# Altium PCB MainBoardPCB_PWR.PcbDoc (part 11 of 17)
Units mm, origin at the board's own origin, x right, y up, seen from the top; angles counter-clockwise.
Board outline 333.63 x 349.38 mm, 16 copper layers (L1, L2 (GND), L3 (Sign), L4 (GND), L5 (Sign), L6 (PWR/GND), L7(PWR/GND), L8 (PWR/GND), L9 (PWR/GND), L10 (PWR/GND), L11 (PWR/GND), L12 (Sign), L13 (GND), L14 (Sign), L15 (GND), L16), stack 2.503 mm thick; 2187 components, 1615 nets, 7987 pads, 1695 vias.
Unrouted connection lines stored in the file: 4757.
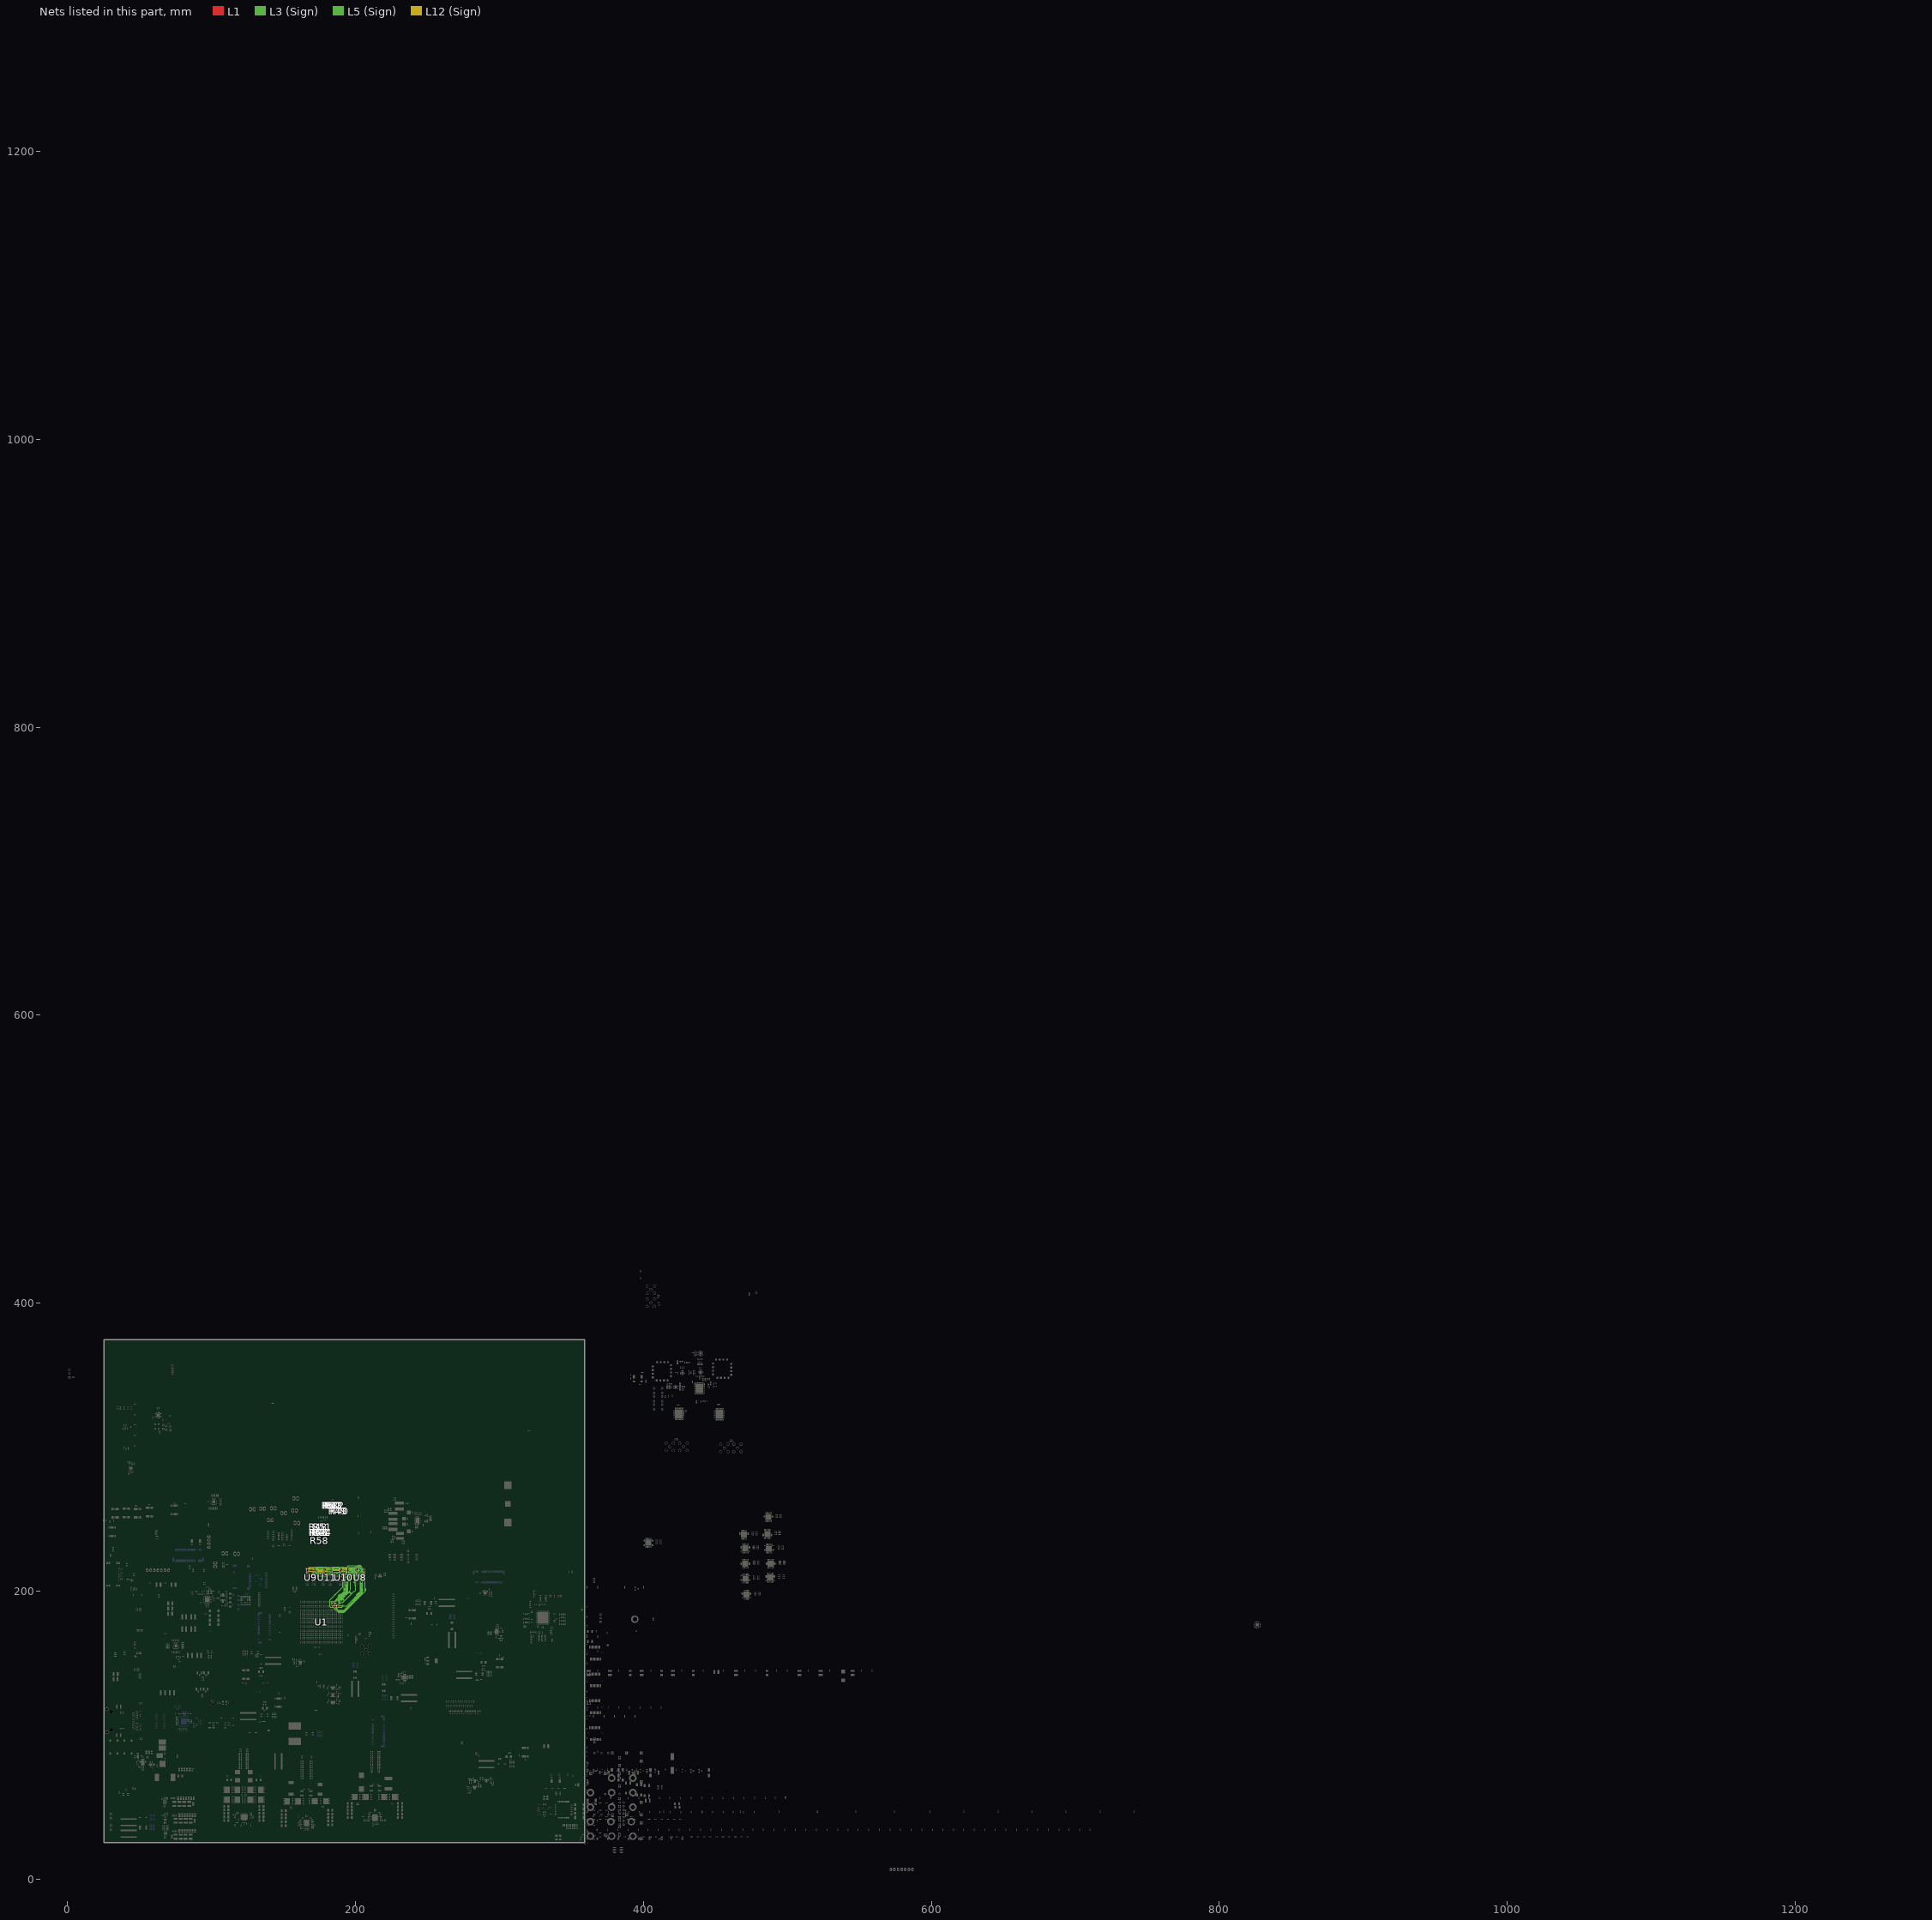
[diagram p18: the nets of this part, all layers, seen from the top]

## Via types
v1: diameter 0.5, hole 0.2, L1 to L16, 786 vias
v2: diameter 0.5/0.35/0.35/0.35/0.35/0.35/0.35/0.35/0.35/0.35/0.35/0.35/0.35/0.35/0.35/0.5 (per signal layer), hole 0.15, L1 to L16, tented both sides, 164 vias
v3: diameter 2.54, hole 1.02, L1 to L16, 152 vias
v4: diameter 0.5/0.35/0.35/0.35/0.35/0.35/0.35/0.35/0.35/0.35/0.35/0.35/0.35/0.35/0.35/0.5 (per signal layer), hole 0.2, L1 to L16, tented both sides, 100 vias
v5: diameter 0.45, hole 0.15, L1 to L16, 79 vias
v6: diameter 0.35/0/0.35 (per signal layer), hole 0.127, L1 to L3 (Sign), tented both sides, 78 vias
v7: diameter 0.45/0.45/0.45/0.45/0.45/0.45/0.45/0.45/0.45/0.45/0.45/0.45/0.45/0.45/0.45/0.45 (per signal layer), hole 0.15, L1 to L16, 65 vias
v8: diameter 0.4, hole 0.15, L1 to L16, 61 vias
v9: diameter 0.2, hole 0.1, L1 to L16, 35 vias
v10: diameter 0.5, hole 0.2, L1 to L16, tented both sides, 32 vias
v11: diameter 0.2/0/0.2 (per signal layer), hole 0.1, L1 to L3 (Sign), 28 vias
v12: diameter 0.4, hole 0.2, L1 to L16, 16 vias
v13: diameter 0.25, hole 0.2, L1 to L16, 16 vias
v14: diameter 0.3, hole 0.2, L1 to L16, 15 vias
v15: diameter 0.5/0.35/0.35/0.35/0.35/0.35/0.35/0.35/0.35/0.35/0.35/0.35/0.35/0.35/0.35/0.45 (per signal layer), hole 0.15, L1 to L16, tented both sides, 10 vias
v16: diameter 5, hole 3, L1 to L16, 9 vias
v17: diameter 0.2/0/0.2 (per signal layer), hole 0.1, L1 to L3 (Sign), tented both sides, 9 vias
v18: diameter 0.35/0/0.35 (per signal layer), hole 0.127, L1 to L3 (Sign), 7 vias
v19: diameter 0.35/0/0.35 (per signal layer), hole 0.127, L14 (Sign) to L16, tented both sides, 5 vias
v20: diameter 1.65, hole 1.65, L1 to L16, 4 vias
v21: diameter 1.15, hole 1.15, L1 to L16, 4 vias
v22: diameter 0.35, hole 0.127, L1 to L2 (GND), 2 vias
v23: diameter 0.4, hole 0.2, L1 to L16, tented both sides, 2 vias
v24: diameter 0.35, hole 0.127, L1 to L2 (GND), tented both sides, 2 vias
v25: diameter 0.508, hole 0.127, L1 to L2 (GND), 2 vias
v26: diameter 0.508, hole 0.127, L2 (GND) to L3 (Sign), 2 vias
v27: diameter 0.35, hole 0.127, L3 (Sign) to L6 (PWR/GND), tented both sides, 2 vias
v28: diameter 0.5, hole 0.2, L3 (Sign) to L6 (PWR/GND), tented both sides, 2 vias
v29: diameter 5.5, hole 3.5, L1 to L16, 1 vias
v30: diameter 0.45/0.45/0.45 (per signal layer), hole 0.15, L1 to L3 (Sign), 1 vias
v31: diameter 0.35/0.35/0.35 (per signal layer), hole 0.127, L1 to L3 (Sign), tented both sides, 1 vias
v32: diameter 0.45/0/0.45 (per signal layer), hole 0.15, L1 to L3 (Sign), tented both sides, 1 vias
v33: diameter 0.45/0/0.45 (per signal layer), hole 0.2, L14 (Sign) to L16, tented both sides, 1 vias
v34: diameter 0.35, hole 0.127, L2 (GND) to L3 (Sign), 1 vias

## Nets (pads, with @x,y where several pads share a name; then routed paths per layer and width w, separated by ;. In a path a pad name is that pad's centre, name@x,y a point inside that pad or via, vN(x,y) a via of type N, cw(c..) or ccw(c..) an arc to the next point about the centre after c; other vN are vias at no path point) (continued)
DDR4_A5: R41.1 U1.AK27 U8.P5 U9.P5 U10.P5 U11.P5 | length 97.8
  L1 w0.116: U9.P5@166.406,213.848 166.802,214.245 v2(166.805,214.245) ; U11.P5@177.866,213.848 178.263,214.245 v2(178.265,214.245) ; U10.P5@189.327,213.848 189.723,214.245 v2(189.726,214.245) ; U1.AK27@190.927,189.927 v6(191.414,190.414) ; v2(200.384,214.252) U8.P5@200.787,213.848
  L12 (Sign) w0.092: 165.877,214.648 166.281,214.245 ; v2@166.802,214.245 166.281,214.245 ; v2@178.263,214.245 173.921,214.245 ; 195.936,214.77 195.787,214.77 ; v2@200.391,214.245 199.872,214.245 199.347,214.77 199.123,214.77 198.765,214.77 cw(c198.765,214.859) 198.675,214.859 198.675,215.005 ccw(c198.586,215.005) 198.586,215.094 198.317,215.094 ccw(c198.317,215.005) 198.228,215.005 198.228,214.859 cw(c198.138,214.859) 198.138,214.77 197.869,214.77 cw(c197.869,214.859) 197.78,214.859 197.78,215.005 ccw(c197.69,215.005) 197.69,215.094 197.422,215.094 ccw(c197.422,215.005) 197.332,215.005 197.332,214.77 197.332,214.235 cw(c197.242,214.235) 197.242,214.145 196.974,214.145 cw(c196.974,214.235) 196.884,214.235 196.884,214.68 ccw(c196.795,214.68) 196.795,214.77 196.05,214.77 195.787,214.77 ; 166.281,214.245 v2(166.805,214.245) 166.995,214.435 167.219,214.435 167.372,214.588 167.83,214.588 168.709,215.468 172.697,215.468 173.921,214.245 ; 173.921,214.245 178.583,214.245 ; 173.921,214.245 v2(178.265,214.245) 178.583,214.245 ; 178.583,214.245 178.981,214.643 179.832,214.643 180.657,215.468 183.655,215.468 184.366,214.757 188.689,214.757 189.202,214.245 v2(189.726,214.245) 189.916,214.435 190.139,214.435 190.293,214.588 190.75,214.588 191.63,215.468 191.694,215.468 194.424,215.468 195.089,215.468 195.787,214.77
  L3 (Sign) w0.092: v6(191.414,190.414) 191.056,190.055 189.852,190.055 189.698,189.901 189.135,189.901 188.921,190.115 188.437,190.115 188.249,190.304 188.249,190.569 188.437,190.758 188.486,190.758 188.862,191.133 188.862,191.316 189.116,191.57 189.116,191.687 188.963,191.839 188.963,191.855 188.709,192.109 188.709,192.659 188.093,193.275 188.093,193.575 188.164,193.645 ccw(c188.093,193.715) 188.164,193.785 188.158,193.791 cw(c188.228,193.861) 188.158,193.931 188.298,194.072 cw(c188.368,194.002) 188.438,194.072 188.514,193.996 188.549,193.961 ccw(c188.619,194.031) 188.69,193.961 188.83,194.101 ccw(c188.76,194.172) 188.83,194.242 188.795,194.277 188.719,194.353 cw(c188.789,194.423) 188.719,194.493 188.86,194.633 cw(c188.93,194.563) 189,194.633 189.076,194.557 189.319,194.314 ccw(c189.389,194.385) 189.459,194.314 189.6,194.455 ccw(c189.529,194.525) 189.6,194.595 189.357,194.838 189.281,194.914 cw(c189.351,194.984) 189.281,195.054 189.421,195.195 cw(c189.491,195.125) 189.561,195.195 189.637,195.119 189.88,194.876 ccw(c189.95,194.946) 190.021,194.876 190.161,195.016 ccw(c190.091,195.086) 190.161,195.157 189.918,195.399 189.842,195.475 cw(c189.912,195.546) 189.842,195.616 189.982,195.756 cw(c190.053,195.686) 190.123,195.756 190.199,195.68 190.442,195.437 ccw(c190.512,195.507) 190.582,195.437 190.722,195.578 ccw(c190.652,195.648) 190.722,195.718 190.48,195.961 190.404,196.037 cw(c190.474,196.107) 190.403,196.177 190.544,196.318 cw(c190.614,196.247) 190.684,196.318 190.76,196.242 191.003,195.999 ccw(c191.073,196.069) 191.144,195.999 191.284,196.139 ccw(c191.214,196.209) 191.284,196.279 191.041,196.522 190.965,196.598 cw(c191.035,196.668) 190.965,196.739 191.105,196.879 cw(c191.175,196.809) 191.246,196.879 191.322,196.803 191.565,196.56 ccw(c191.635,196.63) 191.705,196.56 191.845,196.7 ccw(c191.775,196.771) 191.845,196.841 191.602,197.084 191.526,197.16 cw(c191.597,197.23) 191.526,197.3 191.667,197.44 cw(c191.737,197.37) 191.807,197.44 191.883,197.364 192.126,197.122 ccw(c192.196,197.192) 192.266,197.122 192.407,197.262 ccw(c192.337,197.332) 192.407,197.402 192.164,197.645 192.088,197.721 cw(c192.158,197.791) 192.088,197.862 192.228,198.002 cw(c192.298,197.932) 192.369,198.002 192.445,197.926 192.687,197.683 ccw(c192.758,197.753) 192.828,197.683 192.968,197.823 ccw(c192.898,197.894) 192.968,197.964 192.725,198.207 192.649,198.283 cw(c192.719,198.353) 192.649,198.423 192.79,198.563 cw(c192.86,198.493) 192.93,198.563 193.006,198.487 193.249,198.244 ccw(c193.319,198.315) 193.389,198.244 193.53,198.385 ccw(c193.459,198.455) 193.53,198.525 193.287,198.768 193.211,198.844 cw(c193.281,198.914) 193.211,198.984 193.351,199.125 cw(c193.421,199.055) 193.491,199.125 193.567,199.049 193.81,198.806 ccw(c193.881,198.876) 193.951,198.806 194.091,198.946 ccw(c194.021,199.016) 194.091,199.087 193.848,199.329 193.772,199.406 cw(c193.842,199.476) 193.772,199.546 193.913,199.686 cw(c193.983,199.616) 194.053,199.686 194.129,199.61 194.372,199.367 ccw(c194.442,199.438) 194.512,199.367 194.653,199.508 ccw(c194.582,199.578) 194.653,199.648 194.48,199.821 cw(c194.55,199.891) 194.48,199.961 194.69,200.172 194.742,200.223 194.742,206.035 195.161,206.454 195.161,206.802 195.944,207.585 195.944,210.015 200.173,214.245 200.391,214.245 v2(200.384,214.252)
DDR4_A6: R43.1 U1.AF27 U8.P2 U9.P2 U10.P2 U11.P2 | length 90.7
  L1 w0.116: U9.P2@171.206,213.848 v2(171.609,214.252) ; U11.P2@182.666,213.848 v2(183.07,214.252) ; U1.AF27@186.927,189.927 v6(187.414,189.44) ; U10.P2@194.127,213.848 v1(194.53,214.252) ; U8.P2@205.587,213.848 v2(205.991,214.252)
  L5 (Sign) w0.092: v2(171.609,214.252) 171.935,214.252 172.314,214.63 179.776,214.63 180.538,213.868 182.113,213.868 182.497,214.252 v2(183.07,214.252) 183.369,214.252 183.747,214.63 191.237,214.63 191.999,213.868 193.573,213.868 193.957,214.252 v1(194.53,214.252) 194.757,214.252 195.153,214.648 195.288,214.648 ccw(c195.288,214.738) 195.377,214.738 195.377,214.812 cw(c195.467,214.812) 195.467,214.902 195.736,214.902 cw(c195.736,214.812) 195.825,214.812 195.825,214.648 195.825,214.484 ccw(c195.915,214.484) 195.915,214.394 196.183,214.394 ccw(c196.183,214.484) 196.273,214.484 196.273,214.648 196.273,214.812 cw(c196.363,214.812) 196.363,214.902 196.631,214.902 cw(c196.631,214.812) 196.721,214.812 196.721,214.648 196.721,214.575 ccw(c196.81,214.575) 196.81,214.485 197.079,214.485 ccw(c197.079,214.575) 197.169,214.575 197.169,214.648 197.169,214.812 cw(c197.258,214.812) 197.258,214.902 197.527,214.902 cw(c197.527,214.812) 197.616,214.812 197.616,214.648 197.616,214.575 ccw(c197.706,214.575) 197.706,214.485 197.975,214.485 ccw(c197.975,214.575) 198.064,214.575 198.064,214.648 198.064,214.812 cw(c198.154,214.812) 198.154,214.902 198.422,214.902 cw(c198.422,214.812) 198.512,214.812 198.512,214.648 198.512,214.575 ccw(c198.602,214.575) 198.602,214.485 198.87,214.485 ccw(c198.87,214.575) 198.96,214.575 198.96,214.648 198.96,214.812 cw(c199.049,214.812) 199.049,214.902 199.318,214.902 cw(c199.318,214.812) 199.408,214.812 199.408,214.648 199.408,214.575 ccw(c199.497,214.575) 199.497,214.485 199.766,214.485 ccw(c199.766,214.575) 199.855,214.575 199.855,214.648 199.855,214.678 cw(c199.945,214.678) 199.945,214.767 200.214,214.767 cw(c200.214,214.678) 200.303,214.678 200.303,214.648 ccw(c200.379,214.648) 200.379,214.573 200.675,214.573 ccw(c200.675,214.648) 200.751,214.648 201.199,214.648 201.199,214.639 ccw(c201.288,214.639) 201.288,214.549 201.557,214.549 ccw(c201.557,214.639) 201.647,214.639 201.647,214.648 201.647,214.812 cw(c201.736,214.812) 201.736,214.902 202.005,214.902 cw(c202.005,214.812) 202.094,214.812 202.094,214.738 ccw(c202.184,214.738) 202.184,214.648 202.578,214.648 202.679,214.648 203.474,213.853 203.608,213.853 cw(c203.608,213.763) 203.698,213.763 ccw(c203.787,213.763) 203.787,213.674 204.056,213.674 ccw(c204.056,213.763) 204.146,213.763 204.146,213.77 cw(c204.229,213.77) 204.229,213.853 205.019,213.853 205.417,214.252 v2(205.991,214.252)
  L3 (Sign) w0.092: v6(187.414,189.44) 187.414,187.388 188.008,186.794 192.221,186.794 197.512,192.086 198.535,193.108 ccw(c198.465,193.179) 198.535,193.249 198.239,193.544 cw(c198.31,193.615) 198.239,193.685 198.38,193.825 cw(c198.45,193.755) 198.52,193.825 198.816,193.529 ccw(c198.886,193.6) 198.956,193.529 199.097,193.67 ccw(c199.026,193.74) 199.097,193.81 198.801,194.106 cw(c198.871,194.176) 198.801,194.246 198.941,194.387 cw(c199.011,194.316) 199.082,194.387 199.377,194.091 ccw(c199.448,194.161) 199.518,194.091 199.658,194.231 ccw(c199.588,194.301) 199.658,194.372 ; 199.658,194.372 199.36,194.67 cw(c199.43,194.74) 199.36,194.81 199.5,194.95 cw(c199.57,194.88) 199.641,194.95 199.939,194.652 ccw(c200.009,194.722) 200.079,194.652 200.219,194.793 ccw(c200.149,194.863) 200.219,194.933 199.921,195.231 cw(c199.992,195.301) 199.921,195.372 200.062,195.512 cw(c200.132,195.442) 200.202,195.512 200.5,195.214 ccw(c200.57,195.284) 200.641,195.214 200.781,195.354 ccw(c200.711,195.424) 200.781,195.494 200.483,195.793 cw(c200.553,195.863) 200.483,195.933 200.623,196.073 cw(c200.693,196.003) 200.764,196.073 201.062,195.775 ccw(c201.132,195.845) 201.202,195.775 201.413,195.986 201.553,196.126 203.54,198.113 203.54,211.094 203.893,211.448 205.346,211.448 205.618,211.72 205.618,212.745 205.321,213.042 205.321,213.884 205.678,214.24 205.979,214.24 v2(205.991,214.252)
DDR4_A7: R45.1 U1.AE27 U8.R5 U9.R5 U10.R5 U11.R5 | length 99.2
  L1 w0.116: U9.R5@166.406,214.648 v2@166.705,214.947 ; v2(166.703,214.947) v2@166.705,214.947 ; v2@166.802,215.045 v2@166.705,214.947 ; U11.R5@177.866,214.648 178.263,215.045 v2(178.265,215.045) ; U1.AE27@185.927,189.927 v6(186.414,190.414) v6@186.414,190.44 ; U10.R5@189.327,214.648 189.723,215.045 v2(189.726,215.045) ; v2(200.384,215.052) U8.R5@200.787,214.648
  L12 (Sign) w0.092: 165.885,215.448 166.385,214.947 v2(166.703,214.947) 166.708,214.947 168.129,216.368 172.635,216.368 173.959,215.045 ; v2@178.263,215.045 173.959,215.045 ; v2@189.629,214.947 v2(189.726,215.045) ; v2@200.384,215.045 199.979,215.045 199.053,215.97 198.996,216.027 198.862,216.027 ccw(c198.862,215.937) 198.772,215.937 198.772,215.67 cw(c198.683,215.67) 198.683,215.58 198.414,215.58 cw(c198.414,215.67) 198.325,215.67 198.325,216.027 198.325,216.206 ccw(c198.235,216.206) 198.235,216.296 197.966,216.296 ccw(c197.966,216.206) 197.877,216.206 197.877,216.027 197.877,215.67 cw(c197.787,215.67) 197.787,215.58 197.519,215.58 cw(c197.519,215.67) 197.429,215.67 197.429,215.937 ccw(c197.339,215.937) 197.339,216.027 196.888,216.027 195.897,216.027 195.556,216.368 191.049,216.368 v2(189.726,215.045) ; 173.959,215.045 v2(178.265,215.045) v2@178.456,215.045 ; 173.959,215.045 v2@178.456,215.045 ; v2@178.456,215.045 178.778,215.367 179.807,215.367 180.861,216.421 183.381,216.421 184.537,215.265 189.505,215.265 v2(189.726,215.045)
  L3 (Sign) w0.092: v6(186.414,190.414) 186.414,190.462 186.145,190.732 184.949,191.927 184.949,192.645 185.205,192.901 186.3,192.901 187.129,193.718 187.983,194.561 cw(c188.041,194.502) 188.1,194.56 ; 188.094,194.566 188.099,194.561 ; 188.093,194.567 ccw(c188.164,194.636) 188.233,194.566 188.375,194.705 ccw(c188.305,194.776) 188.376,194.845 188.324,194.897 188.085,195.14 cw(c188.156,195.209) 188.086,195.28 188.228,195.419 cw(c188.298,195.349) 188.368,195.418 188.607,195.176 188.654,195.128 ccw(c188.725,195.198) 188.795,195.127 188.936,195.266 ccw(c188.866,195.337) 188.937,195.407 188.89,195.455 188.874,195.47 cw(c188.945,195.54) 188.875,195.611 189.017,195.75 cw(c189.086,195.68) 189.157,195.749 189.172,195.733 189.223,195.683 ccw(c189.293,195.752) 189.363,195.682 189.504,195.821 ccw(c189.435,195.892) 189.505,195.961 cw(c189.556,196.011) 189.506,196.062 189.597,196.151 189.657,196.211 189.894,196.445 cw(c189.939,196.4) 189.984,196.444 ; 189.978,196.45 189.983,196.445 ; 189.978,196.451 ccw(c190.048,196.521) 190.118,196.45 190.259,196.59 ccw(c190.19,196.66) 190.26,196.73 190.222,196.768 189.917,197.078 cw(c189.987,197.148) 189.918,197.219 190.059,197.358 cw(c190.129,197.287) 190.199,197.357 190.505,197.047 190.539,197.013 ccw(c190.61,197.082) 190.679,197.012 190.821,197.151 ccw(c190.751,197.222) 190.822,197.291 190.788,197.326 190.513,197.605 cw(c190.583,197.675) 190.514,197.745 190.655,197.885 cw(c190.725,197.814) 190.795,197.884 191.071,197.604 191.1,197.574 ccw(c191.171,197.644) 191.241,197.573 191.382,197.712 ccw(c191.313,197.783) 191.383,197.853 191.353,197.883 191.074,198.167 cw(c191.144,198.237) 191.075,198.307 191.216,198.447 cw(c191.286,198.376) 191.356,198.446 191.636,198.162 191.662,198.136 ccw(c191.733,198.205) 191.802,198.135 191.944,198.274 ccw(c191.874,198.345) 191.945,198.414 191.919,198.441 191.635,198.728 cw(c191.706,198.798) 191.636,198.869 191.777,199.008 cw(c191.847,198.937) 191.918,199.007 192.201,198.719 192.223,198.697 ccw(c192.294,198.767) 192.364,198.696 192.505,198.835 ccw(c192.435,198.906) 192.506,198.976 192.484,198.998 192.196,199.29 cw(c192.267,199.36) 192.197,199.43 192.339,199.57 cw(c192.409,199.499) 192.479,199.569 192.767,199.277 192.792,199.252 ccw(c192.862,199.321) 192.932,199.251 193.073,199.39 ccw(c193.004,199.461) 193.074,199.53 cw(c193.099,199.555) 193.075,199.58 193.191,199.695 193.294,199.797 ; 193.294,199.896 193.294,199.797 ; v2(200.384,215.052) 200.142,215.052 194.996,209.906 193.656,209.906 193.294,209.544 193.294,208.826 192.396,207.928 192.396,206.626 193.294,205.727 193.294,205.529 cw(c193.294,205.471) 193.352,205.471 193.352,205.19 cw(c193.294,205.19) 193.294,205.132 193.294,204.735 cw(c193.294,204.678) 193.35,204.678 193.35,204.394 cw(c193.294,204.394) 193.294,204.338 193.16,204.338 ccw(c193.16,204.238) 193.061,204.238 193.061,204.04 ccw(c193.16,204.04) 193.16,203.941 193.294,203.941 cw(c193.294,203.884) 193.35,203.884 193.35,203.6 cw(c193.294,203.6) 193.294,203.544 193.294,203.147 cw(c193.294,203.09) 193.35,203.09 193.35,202.806 cw(c193.294,202.806) 193.294,202.75 193.18,202.75 ccw(c193.18,202.65) 193.08,202.65 193.08,202.452 ccw(c193.18,202.452) 193.18,202.353 193.294,202.353 cw(c193.294,202.296) 193.35,202.296 193.35,202.012 cw(c193.294,202.012) 193.294,201.956 192.495,201.956 ccw(c192.495,201.856) 192.396,201.856 192.396,201.658 ccw(c192.495,201.658) 192.495,201.559 193.294,201.559 cw(c193.294,201.502) 193.35,201.502 193.35,201.218 cw(c193.294,201.218) 193.294,201.162 192.495,201.162 ccw(c192.495,201.062) 192.396,201.062 192.396,200.864 ccw(c192.495,200.864) 192.495,200.765 193.294,200.765 193.81,200.765 cw(c193.81,200.665) 193.909,200.665 193.909,200.467 cw(c193.81,200.467) 193.81,200.368 193.393,200.368 ccw(c193.393,200.268) 193.294,200.268 193.294,199.971 193.294,199.797
DDR4_A8: R47.1 U1.AF26 U8.R2 U9.R2 U10.R2 U11.R2 | length 93.6
  L1 w0.116: U9.R2@171.206,214.648 v2(171.609,215.052) ; U11.R2@182.666,214.648 v2(183.07,215.052) ; v6(186.44,189.414) U1.AF26@186.927,188.927 ; U10.R2@194.127,214.648 v1(194.53,215.052) ; U8.R2@205.587,214.648 v2(205.991,215.052)
  L5 (Sign) w0.092: 170.382,214.731 170.703,215.052 v2(171.609,215.052) 172.872,216.315 179.303,216.315 180.97,214.648 181.866,214.648 182.27,215.052 v2(183.07,215.052) 184.333,216.315 190.764,216.315 192.43,214.648 193.327,214.648 193.73,215.052 v1(194.53,215.052) 194.972,215.494 195.123,215.644 195.123,216.23 195.207,216.315 195.415,216.315 195.549,216.315 ccw(c195.549,216.404) 195.639,216.404 195.639,216.512 cw(c195.728,216.512) 195.728,216.601 195.997,216.601 cw(c195.997,216.512) 196.087,216.512 196.087,216.404 ccw(c196.176,216.404) 196.176,216.315 197.307,216.315 199.517,216.315 ccw(c199.517,216.399) 199.601,216.399 199.601,216.428 cw(c199.691,216.428) 199.691,216.518 199.96,216.518 cw(c199.96,216.428) 200.049,216.428 200.049,216.315 200.049,216.201 ccw(c200.139,216.201) 200.139,216.111 200.407,216.111 ccw(c200.407,216.201) 200.497,216.201 200.497,216.315 200.497,216.428 cw(c200.587,216.428) 200.587,216.518 200.855,216.518 cw(c200.855,216.428) 200.945,216.428 200.945,216.315 200.945,216.255 ccw(c201.034,216.255) 201.034,216.165 201.303,216.165 ccw(c201.303,216.255) 201.393,216.255 201.393,216.315 201.393,216.428 cw(c201.482,216.428) 201.482,216.518 201.751,216.518 cw(c201.751,216.428) 201.84,216.428 201.84,216.315 201.84,216.201 ccw(c201.93,216.201) 201.93,216.111 202.199,216.111 ccw(c202.199,216.201) 202.288,216.201 202.288,216.315 202.288,216.428 cw(c202.378,216.428) 202.378,216.518 202.646,216.518 cw(c202.646,216.428) 202.736,216.428 202.736,216.315 202.736,216.201 ccw(c202.826,216.201) 202.826,216.111 203.094,216.111 ccw(c203.094,216.201) 203.184,216.201 203.184,216.225 cw(c203.273,216.225) 203.273,216.315 203.408,216.315 203.568,216.154 203.568,215.557 203.975,215.151 204.015,215.151 204.063,215.103 204.063,214.695 204.109,214.648 204.787,214.648 205.191,215.052 v2(205.991,215.052)
  L3 (Sign) w0.092: v6(186.44,189.414) 186.44,188.977 186.069,188.606 186.069,188.15 188.409,185.809 191.829,185.809 204.813,198.793 204.813,200.292 204.813,200.391 ccw(c204.713,200.391) 204.713,200.49 204.448,200.49 cw(c204.448,200.589) 204.349,200.589 204.349,200.788 cw(c204.448,200.788) 204.448,200.887 204.813,200.887 205.177,200.887 ccw(c205.177,200.986) 205.276,200.986 205.276,201.185 ccw(c205.177,201.185) 205.177,201.284 204.813,201.284 204.448,201.284 cw(c204.448,201.383) 204.349,201.383 204.349,201.582 cw(c204.448,201.582) 204.448,201.681 204.713,201.681 ccw(c204.713,201.78) 204.813,201.78 204.813,203.035 204.813,210.362 205.054,210.604 205.543,210.604 206.158,211.219 206.158,212.676 205.573,213.261 205.573,213.688 205.816,213.931 205.857,213.931 205.858,213.931 206.124,213.931 206.125,213.931 206.134,213.931 206.311,214.109 206.311,214.118 206.312,214.385 206.311,214.731 v2(205.991,215.052)
DDR4_A9: R48.1 U1.AG26 U8.R4 U9.R4 U10.R4 U11.R4 | length 89.3
  L1 w0.116: U9.R4@167.206,214.648 167.602,215.045 167.605,215.042 v2(167.605,214.909) ; U11.R4@178.666,214.648 179.063,215.045 v2(179.065,215.045) ; U1.AG26@187.927,188.927 v6(188.414,189.414) ; U10.R4@190.127,214.648 190.523,215.045 v1(190.526,215.045) ; v1(201.184,215.052) U8.R4@201.587,214.648
  L12 (Sign) w0.092: v2(167.605,214.909) 167.643,214.909 168.91,216.176 172.434,216.176 173.929,214.681 178.701,214.681 v2(179.065,215.045) 179.762,215.045 180.946,216.229 183.301,216.229 184.488,215.041 188.806,215.041 189.221,214.626 189.836,214.626 190.254,215.045 v1(190.526,215.045) 191.657,216.176 191.792,216.176 cw(c191.792,216.087) 191.881,216.087 191.881,215.762 ccw(c191.971,215.762) 191.971,215.672 192.24,215.672 ccw(c192.24,215.762) 192.329,215.762 192.329,216.087 cw(c192.419,216.087) 192.419,216.176 192.777,216.176 193.225,216.176 193.583,216.176 cw(c193.583,216.087) 193.673,216.087 193.673,215.762 ccw(c193.762,215.762) 193.762,215.672 194.031,215.672 ccw(c194.031,215.762) 194.12,215.762 194.12,216.087 cw(c194.21,216.087) 194.21,216.176 194.589,216.176 195.354,216.176 196.215,215.316 196.349,215.316 ccw(c196.349,215.405) 196.439,215.405 cw(c196.528,215.405) 196.528,215.495 196.797,215.495 cw(c196.797,215.405) 196.887,215.405 ccw(c196.976,215.405) 196.976,215.316 197.079,215.316 199.35,215.316 199.942,214.724 200.856,214.724 v1(201.184,215.052)
  L3 (Sign) w0.092: v6(188.414,189.414) 188.414,189.866 188.057,190.224 188.057,190.649 188.357,190.949 188.406,190.949 188.659,191.202 188.659,191.339 188.662,191.343 188.662,191.387 188.771,191.497 188.771,191.776 188.583,191.964 188.567,191.964 188.517,192.014 188.517,192.568 187.901,193.184 187.901,193.947 194.101,200.146 194.101,200.939 194.101,200.952 ccw(c194.002,200.952) 194.002,201.051 193.642,201.051 cw(c193.642,201.151) 193.542,201.151 193.542,201.349 cw(c193.642,201.349) 193.642,201.448 194.101,201.448 194.394,201.448 ccw(c194.394,201.548) 194.494,201.548 194.494,201.746 ccw(c194.394,201.746) 194.394,201.845 194.101,201.845 193.642,201.845 cw(c193.642,201.945) 193.542,201.945 193.542,202.143 cw(c193.642,202.143) 193.642,202.242 194.101,202.242 194.394,202.242 ccw(c194.394,202.342) 194.494,202.342 194.494,202.54 ccw(c194.394,202.54) 194.394,202.639 194.101,202.639 193.642,202.639 cw(c193.642,202.739) 193.542,202.739 193.542,202.937 cw(c193.642,202.937) 193.642,203.036 194.101,203.036 194.394,203.036 ccw(c194.394,203.136) 194.494,203.136 194.494,203.334 ccw(c194.394,203.334) 194.394,203.433 194.101,203.433 193.642,203.433 cw(c193.642,203.533) 193.542,203.533 193.542,203.731 cw(c193.642,203.731) 193.642,203.83 194.101,203.83 194.394,203.83 ccw(c194.394,203.93) 194.494,203.93 194.494,204.128 ccw(c194.394,204.128) 194.394,204.227 194.101,204.227 193.642,204.227 cw(c193.642,204.327) 193.542,204.327 193.542,204.525 cw(c193.642,204.525) 193.642,204.624 194.101,204.624 194.394,204.624 ccw(c194.394,204.724) 194.494,204.724 194.494,204.922 ccw(c194.394,204.922) 194.394,205.021 194.2,205.021 cw(c194.2,205.121) 194.101,205.121 194.101,205.319 cw(c194.2,205.319) 194.2,205.418 194.394,205.418 ccw(c194.394,205.518) 194.494,205.518 194.494,205.716 ccw(c194.394,205.716) 194.394,205.815 194.2,205.815 cw(c194.2,205.915) 194.101,205.915 194.101,206.014 195.752,207.664 195.752,207.764 ccw(c195.652,207.764) 195.652,207.863 194.338,207.863 cw(c194.338,207.962) 194.239,207.962 194.239,208.161 cw(c194.338,208.161) 194.338,208.26 195.652,208.26 ccw(c195.652,208.359) 195.752,208.359 195.752,208.558 ccw(c195.652,208.558) 195.652,208.657 194.989,208.657 cw(c194.989,208.756) 194.889,208.756 194.889,208.954 cw(c194.989,208.954) 194.989,209.054 195.652,209.054 ccw(c195.652,209.153) 195.752,209.153 195.752,209.351 ccw(c195.652,209.351) 195.652,209.451 195.251,209.451 cw(c195.251,209.55) 195.151,209.55 195.151,209.748 cw(c195.251,209.748) 195.251,209.848 195.652,209.848 ccw(c195.652,209.947) 195.752,209.947 195.752,210.071 195.752,210.183 200.211,214.643 200.775,214.643 v1(201.184,215.052)
DDR4_A10: R49.1 U1.AE29 U8.M3 U9.M3 U10.M3 U11.M3 | length 90.7
  L1 w0.116: v2(170.002,212.652) U9.M3@170.406,212.248 ; v2(181.463,212.652) U11.M3@181.866,212.248 ; v6(185.44,192.414) U1.AE29@185.927,191.927 ; v2(192.923,212.652) U10.M3@193.327,212.248 ; v15(204.384,212.652) U8.M3@204.787,212.248
  L5 (Sign) w0.092: v2(170.002,212.652) 170.239,212.889 170.605,212.889 170.772,213.055 172.042,213.055 172.842,212.255 179.459,212.255 179.855,212.652 v2(181.463,212.652) 182.306,212.652 182.71,213.055 183.502,213.055 184.302,212.255 190.919,212.255 191.316,212.652 v2(192.923,212.652) 192.93,212.645 193.871,212.645 194.23,213.004 195.059,213.004 195.434,212.63 195.568,212.63 ccw(c195.568,212.719) 195.658,212.719 195.658,212.844 cw(c195.747,212.844) 195.747,212.933 196.016,212.933 cw(c196.016,212.844) 196.106,212.844 196.106,212.63 196.106,212.416 ccw(c196.195,212.416) 196.195,212.326 196.464,212.326 ccw(c196.464,212.416) 196.553,212.416 196.553,212.63 196.553,212.844 cw(c196.643,212.844) 196.643,212.933 196.912,212.933 cw(c196.912,212.844) 197.001,212.844 197.001,212.63 197.001,212.416 ccw(c197.091,212.416) 197.091,212.326 197.359,212.326 ccw(c197.359,212.416) 197.449,212.416 197.449,212.63 197.449,212.844 cw(c197.539,212.844) 197.539,212.933 197.807,212.933 cw(c197.807,212.844) 197.897,212.844 197.897,212.63 197.897,212.416 ccw(c197.986,212.416) 197.986,212.326 198.255,212.326 ccw(c198.255,212.416) 198.345,212.416 198.345,212.63 198.345,212.762 cw(c198.434,212.762) 198.434,212.852 198.703,212.852 cw(c198.703,212.762) 198.792,212.762 198.792,212.719 ccw(c198.882,212.719) 198.882,212.63 200.457,212.63 200.654,212.63 201.028,212.255 202.07,212.255 202.466,212.652 202.646,212.652 cw(c202.646,212.532) 202.766,212.532 202.766,212.301 ccw(c202.886,212.301) 202.886,212.181 203.246,212.181 ccw(c203.246,212.301) 203.366,212.301 203.366,212.652 203.366,212.744 cw(c203.486,212.744) 203.486,212.864 203.847,212.864 cw(c203.847,212.744) 203.967,212.744 203.967,212.685 ccw(c204,212.685) 204,212.652 v15(204.384,212.652)
  L3 (Sign) w0.092: v6(185.44,192.414) 185.525,192.329 185.525,191.783 187.735,189.573 187.735,189.119 188.028,188.826 189.842,188.826 189.984,188.968 190.599,188.968 190.66,189.029 191.267,189.636 193.756,189.636 198.92,194.8 198.92,194.805 200.279,196.164 200.611,196.496 cw(c200.681,196.426) 200.751,196.496 201.013,196.234 ccw(c201.083,196.304) 201.154,196.234 201.294,196.375 ccw(c201.224,196.445) 201.294,196.515 200.962,196.847 200.63,197.179 cw(c200.7,197.249) 200.63,197.319 200.77,197.46 cw(c200.84,197.39) 200.91,197.46 201.242,197.128 201.575,196.796 ccw(c201.645,196.866) 201.715,196.796 201.855,196.936 ccw(c201.785,197.006) 201.855,197.076 201.523,197.408 201.191,197.741 cw(c201.261,197.811) 201.191,197.881 201.331,198.021 cw(c201.402,197.951) 201.472,198.021 201.804,197.689 202.136,197.357 ccw(c202.206,197.427) 202.276,197.357 202.417,197.497 ccw(c202.347,197.568) 202.417,197.638 202.085,197.97 201.753,198.302 cw(c201.823,198.372) 201.753,198.442 201.893,198.583 cw(c201.963,198.513) 202.033,198.583 202.365,198.251 202.697,197.918 ccw(c202.768,197.989) 202.838,197.918 202.978,198.059 ccw(c202.908,198.129) 202.978,198.199 202.646,198.531 202.314,198.863 cw(c202.384,198.934) 202.314,199.004 202.454,199.144 cw(c202.525,199.074) 202.595,199.144 202.927,198.812 203.01,198.729 ccw(c203.08,198.799) 203.151,198.729 203.291,198.869 ccw(c203.221,198.939) 203.291,199.009 203.278,199.023 cw(c203.348,199.093) 203.278,199.163 203.348,199.233 203.348,211.174 204.384,212.21 v15(204.384,212.652)
DDR4_A11: R50.1 U1.AE28 U8.T2 U9.T2 U10.T2 U11.T2 | length 91.4
  L1 w0.116: U9.T2@171.206,215.448 v2(171.609,215.852) ; U11.T2@182.666,215.448 v2(183.07,215.852) ; v6(185.44,190.44) U1.AE28@185.927,190.927 ; U10.T2@194.127,215.448 v1(194.53,215.852) ; v2(205.184,215.852) U8.T2@205.587,215.448
  L5 (Sign) w0.092: v2(171.609,215.852) 172.269,216.511 172.526,216.511 172.713,216.699 179.706,216.699 179.894,216.511 180.118,216.511 181.173,215.456 181.874,215.456 182.27,215.852 v2(183.07,215.852) 183.729,216.511 183.986,216.511 184.174,216.699 191.167,216.699 191.354,216.511 191.578,216.511 192.634,215.456 193.334,215.456 193.73,215.852 v1(194.53,215.852) 194.53,217.492 194.653,217.614 195.25,217.614 199.479,217.614 201.217,217.614 cw(c201.217,217.525) 201.306,217.525 201.306,217.428 ccw(c201.396,217.428) 201.396,217.338 201.664,217.338 ccw(c201.664,217.428) 201.754,217.428 201.754,217.614 201.754,217.801 cw(c201.844,217.801) 201.844,217.891 202.112,217.891 cw(c202.112,217.801) 202.202,217.801 202.202,217.614 202.202,217.428 ccw(c202.291,217.428) 202.291,217.338 202.56,217.338 ccw(c202.56,217.428) 202.65,217.428 202.65,217.614 202.65,217.801 cw(c202.739,217.801) 202.739,217.891 203.008,217.891 cw(c203.008,217.801) 203.097,217.801 203.097,217.614 203.097,217.428 ccw(c203.187,217.428) 203.187,217.338 203.456,217.338 ccw(c203.456,217.428) 203.545,217.428 203.545,217.525 cw(c203.635,217.525) 203.635,217.614 203.769,217.614 204.063,217.321 204.063,215.719 204.326,215.456 204.795,215.456 v2(205.184,215.852)
  L3 (Sign) w0.092: v6@185.378,190.378 v6(185.44,190.44) 185.091,190.44 183.579,188.927 182.473,188.927 182.119,189.281 182.119,189.316 182.105,189.329 182.105,189.529 182.119,189.542 182.119,189.547 182.307,189.735 182.313,189.735 182.397,189.82 182.397,193.954 185.855,197.412 185.925,197.482 ccw(c185.855,197.552) 185.925,197.622 185.917,197.63 cw(c185.987,197.7) 185.917,197.771 186.057,197.911 cw(c186.128,197.841) 186.198,197.911 186.206,197.903 ccw(c186.276,197.973) 186.346,197.903 186.836,198.393 187.316,198.873 191.275,202.832 191.275,209.76 191.847,210.332 191.847,211.344 192.657,212.153 195.58,212.153 200.52,217.094 203.594,217.094 204.515,216.173 204.863,216.173 v2(205.184,215.852)
DDR4_A12: R51.1 U1.AH29 U8.M4 U9.M4 U10.M4 U11.M4 | length 90.3
  L1 w0.116: U9.M4@167.206,212.248 167.602,212.645 v2(167.605,212.645) ; U11.M4@178.666,212.248 179.063,212.645 v2(179.065,212.645) ; U1.AH29@188.927,191.927 v6(189.414,192.414) ; U10.M4@190.127,212.248 190.523,212.645 v2(190.526,212.645) ; U8.M4@201.587,212.248 201.984,212.645 v2(201.986,212.645) v2@201.94,212.69
  L12 (Sign) w0.092: 165.888,212.638 166.203,212.324 167.076,212.324 167.397,212.645 v2(167.605,212.645) 167.605,212.639 168.141,212.103 177.679,212.103 177.825,212.248 178.639,212.248 179.036,212.645 v2(179.065,212.645) 179.798,212.645 180.438,212.004 184.14,212.004 185.217,213.081 188.366,213.081 189.123,212.324 189.997,212.324 190.318,212.645 v2(190.526,212.645) 191.067,212.103 191.101,212.103 191.221,211.983 191.415,211.983 ccw(c191.415,212.013) 191.445,212.013 cw(c191.534,212.013) 191.534,212.103 191.803,212.103 cw(c191.803,212.013) 191.893,212.013 191.893,211.983 191.893,211.655 ccw(c191.982,211.655) 191.982,211.566 192.251,211.566 ccw(c192.251,211.655) 192.34,211.655 192.34,211.983 cw(c192.43,211.983) 192.43,212.073 192.699,212.073 cw(c192.699,211.983) 192.788,211.983 192.788,211.655 ccw(c192.878,211.655) 192.878,211.566 193.146,211.566 ccw(c193.146,211.655) 193.236,211.655 193.236,211.894 cw(c193.326,211.894) 193.326,211.983 194.373,211.983 200.605,211.983 200.787,212.165 201.161,212.165 201.685,212.69 201.94,212.69 v2(201.986,212.645)
  L3 (Sign) w0.092: v6(189.414,192.414) 189.735,192.093 191.258,192.093 198.916,199.752 199.295,199.752 200.04,200.497 200.04,203.663 199.936,203.767 199.936,205.372 199.936,205.629 cw(c200.001,205.629) 200.001,205.693 ; 199.987,205.693 ccw(c199.987,205.793) 200.087,205.793 200.087,205.991 ccw(c199.987,205.991) 199.987,206.09 199.936,206.09 198.933,206.09 cw(c198.933,206.19) 198.834,206.19 198.834,206.388 cw(c198.933,206.388) 198.933,206.487 199.936,206.487 ccw(c199.936,206.564) 200.013,206.564 200.013,206.808 ccw(c199.936,206.808) 199.936,206.884 198.933,206.884 cw(c198.933,206.984) 198.834,206.984 198.834,207.182 cw(c198.933,207.182) 198.933,207.281 199.936,207.281 200.391,207.281 ccw(c200.391,207.381) 200.49,207.381 200.49,207.579 ccw(c200.391,207.579) 200.391,207.678 199.936,207.678 198.933,207.678 cw(c198.933,207.778) 198.834,207.778 198.834,207.976 cw(c198.933,207.976) 198.933,208.075 199.936,208.075 200.345,208.075 ccw(c200.345,208.175) 200.444,208.175 200.444,208.373 ccw(c200.345,208.373) 200.345,208.472 199.936,208.472 198.933,208.472 cw(c198.933,208.572) 198.834,208.572 198.834,208.77 cw(c198.933,208.77) 198.933,208.869 199.936,208.869 199.996,208.869 ccw(c199.996,208.969) 200.095,208.969 200.095,209.167 ccw(c199.996,209.167) 199.996,209.266 199.936,209.266 198.933,209.266 cw(c198.933,209.366) 198.834,209.366 198.834,209.564 cw(c198.933,209.564) 198.933,209.663 199.936,209.663 200.018,209.663 ccw(c200.018,209.763) 200.117,209.763 200.117,209.961 ccw(c200.018,209.961) 200.018,210.06 199.936,210.06 198.933,210.06 cw(c198.933,210.16) 198.834,210.16 198.834,210.358 cw(c198.933,210.358) 198.933,210.457 199.936,210.457 200.448,210.457 ccw(c200.448,210.557) 200.547,210.557 200.547,210.755 ccw(c200.448,210.755) 200.448,210.854 199.936,210.854 199.395,210.854 cw(c199.395,210.954) 199.296,210.954 199.296,211.152 cw(c199.395,211.152) 199.395,211.251 199.936,211.251 200.495,211.251 ccw(c200.495,211.351) 200.594,211.351 200.594,211.549 ccw(c200.495,211.549) 200.495,211.648 200.035,211.648 cw(c200.035,211.748) 199.936,211.748 199.936,211.847 200.337,212.248 201.589,212.248 v2(201.986,212.645) ; 199.988,205.693 200,205.693
DDR4_A13: R53.1 U1.AH28 U8.T5 U9.T5 U10.T5 U11.T5 | length 96.9
  L1 w0.116: U9.T5@166.406,215.448 166.804,215.847 v1(166.804,215.976) ; U11.T5@177.866,215.448 178.263,215.845 v2(178.265,215.845) ; v6(188.57,190.436) 188.57,190.57 U1.AH28@188.927,190.927 ; U10.T5@189.327,215.448 189.725,215.847 v2(189.725,215.976) ; U8.T5@200.787,215.448 201.184,215.845 v2(201.186,215.845)
  L12 (Sign) w0.092: 165.806,215.735 166.048,215.976 v1(166.804,215.976) 167.101,215.976 167.686,216.56 173.04,216.56 173.756,215.845 ; v2@178.263,215.845 173.756,215.845 ; v2(178.265,215.845) 180.005,215.845 ; v2(201.186,215.845) 200.914,215.845 200.78,215.845 ccw(c200.78,215.755) 200.69,215.755 200.69,215.701 cw(c200.601,215.701) 200.601,215.612 200.332,215.612 cw(c200.332,215.701) 200.242,215.701 200.242,215.845 200.242,216.566 ccw(c200.153,216.566) 200.153,216.656 199.884,216.656 ccw(c199.884,216.566) 199.795,216.566 199.795,215.934 cw(c199.705,215.934) 199.705,215.845 199.682,215.845 198.966,216.56 190.606,216.56 190.022,215.976 ; 173.756,215.845 180.005,215.845 ; 180.005,215.845 180.784,216.624 183.528,216.624 184.671,215.481 188.473,215.481 188.968,215.976 ; 188.968,215.976 190.022,215.976 ; 188.968,215.976 v2(189.725,215.976) 190.022,215.976
  L3 (Sign) w0.092: v6(188.57,190.436) 188.57,190.57 189.078,191.078 189.078,191.26 189.378,191.56 189.378,191.696 189.155,191.919 189.155,191.935 188.901,192.189 188.901,193.355 189.323,193.777 189.547,193.777 189.688,193.917 cw(c189.729,193.959) 189.688,194 189.885,194.198 cw(c189.927,194.156) 189.969,194.198 190.406,193.76 ccw(c190.477,193.83) 190.547,193.76 190.687,193.9 ccw(c190.617,193.97) 190.687,194.04 190.249,194.478 cw(c190.291,194.52) 190.249,194.562 190.447,194.759 cw(c190.488,194.718) 190.53,194.759 191.502,193.787 ccw(c191.572,193.857) 191.642,193.787 191.783,193.928 ccw(c191.712,193.998) 191.783,194.068 190.811,195.04 cw(c190.852,195.081) 190.811,195.123 191.008,195.321 cw(c191.05,195.279) 191.091,195.321 191.347,195.065 ccw(c191.417,195.135) 191.487,195.065 191.628,195.205 ccw(c191.558,195.275) 191.628,195.346 191.372,195.601 cw(c191.414,195.643) 191.372,195.684 191.57,195.882 cw(c191.611,195.84) 191.653,195.882 191.909,195.626 ccw(c191.979,195.697) 192.049,195.626 192.189,195.767 ccw(c192.119,195.837) 192.189,195.907 191.934,196.163 cw(c191.975,196.204) 191.934,196.246 192.131,196.443 cw(c192.173,196.402) 192.214,196.443 192.47,196.188 ccw(c192.54,196.258) 192.61,196.188 192.751,196.328 ccw(c192.681,196.398) 192.751,196.469 192.495,196.724 cw(c192.537,196.766) 192.495,196.807 192.693,197.005 cw(c192.734,196.963) 192.776,197.005 193.031,196.749 ccw(c193.102,196.819) 193.172,196.749 193.312,196.89 ccw(c193.242,196.96) 193.312,197.03 193.057,197.286 cw(c193.098,197.327) 193.057,197.369 193.254,197.566 cw(c193.296,197.525) 193.337,197.566 193.593,197.822 193.663,197.892 cw(c193.733,197.822) 193.804,197.892 193.989,197.707 ccw(c194.059,197.777) 194.129,197.707 194.27,197.847 ccw(c194.2,197.917) 194.27,197.988 194.014,198.243 cw(c194.056,198.285) 194.014,198.326 194.212,198.524 cw(c194.253,198.482) 194.295,198.524 194.55,198.268 ccw(c194.621,198.338) 194.691,198.268 194.831,198.409 ccw(c194.761,198.479) 194.831,198.549 194.576,198.805 cw(c194.617,198.846) 194.576,198.888 194.773,199.085 cw(c194.815,199.044) 194.856,199.085 195.112,198.83 ccw(c195.182,198.9) 195.252,198.83 195.393,198.97 ccw(c195.322,199.04) 195.393,199.11 195.137,199.366 cw(c195.179,199.408) 195.137,199.449 195.335,199.647 cw(c195.376,199.605) 195.418,199.647 196.589,198.476 ccw(c196.659,198.546) 196.729,198.476 196.869,198.616 ccw(c196.799,198.686) 196.869,198.757 195.698,199.928 cw(c195.758,199.987) 195.698,200.047 195.859,200.208 cw(c195.919,200.148) 195.979,200.208 196.26,200.489 196.289,200.518 196.71,200.939 196.71,209.779 200.698,213.766 201.506,213.766 201.665,213.926 201.665,214.377 201.853,214.565 ; v2(201.186,215.845) 201.909,215.845 202.146,215.608 202.146,214.858 201.854,214.565
DDR4_ACT_N: R40.1 U1.AD26 U8.L3 U9.L3 U10.L3 U11.L3 | length 91
  L1 w0.116: v2(170.002,211.044) U9.L3@170.406,211.448 ; v2(181.463,211.044) U11.L3@181.866,211.448 ; U1.AD26@184.927,188.927 185.421,189.421 v6(185.547,189.421) ; v2(192.923,211.044) U10.L3@193.327,211.448 ; U8.L3@204.787,211.448 v15(205.191,211.044)
  L5 (Sign) w0.092: v2(170.002,211.044) 170.354,211.396 172.593,211.396 173.373,210.617 180.357,210.617 180.784,211.044 v2(181.463,211.044) 181.925,211.507 183.943,211.507 184.795,210.655 192.225,210.655 192.614,211.044 v2(192.923,211.044) 193.346,211.468 194.723,211.468 ; v15(205.191,211.044) 205.191,211.052 205.505,211.365 205.505,212.008 205.296,212.217 204.94,212.217 204.241,211.518 202.501,211.518 202.197,211.214 200.469,211.214 200.335,211.214 ccw(c200.335,211.124) 200.246,211.124 200.246,210.89 cw(c200.156,210.89) 200.156,210.8 199.887,210.8 cw(c199.887,210.89) 199.798,210.89 199.798,211.214 199.798,211.556 ccw(c199.708,211.556) 199.708,211.646 199.44,211.646 ccw(c199.44,211.556) 199.35,211.556 199.35,211.214 199.35,210.898 cw(c199.26,210.898) 199.26,210.808 198.992,210.808 cw(c198.992,210.898) 198.902,210.898 198.902,211.124 ccw(c198.813,211.124) 198.813,211.214 198.768,211.214 195.008,211.214 194.977,211.214 194.935,211.256 ; 194.723,211.468 194.935,211.256 ; 194.723,211.468 194.935,211.256
  L3 (Sign) w0.092: v6(185.547,189.421) 185.725,189.421 186.081,189.776 186.528,189.776 186.569,189.735 186.573,189.735 186.761,189.547 186.761,188.922 187.155,188.527 187.155,187.342 188.492,186.006 191.746,186.006 203.732,197.992 203.732,198.19 203.732,198.488 cw(c203.831,198.488) 203.831,198.587 204.216,198.587 ccw(c204.216,198.686) 204.315,198.686 204.315,198.885 ccw(c204.216,198.885) 204.216,198.984 203.831,198.984 cw(c203.831,199.083) 203.732,199.083 203.732,199.282 cw(c203.831,199.282) 203.831,199.381 204.216,199.381 ccw(c204.216,199.48) 204.315,199.48 204.315,199.679 ccw(c204.216,199.679) 204.216,199.778 203.831,199.778 cw(c203.831,199.877) 203.732,199.877 203.732,200.076 cw(c203.831,200.076) 203.831,200.175 204.05,200.175 ccw(c204.05,200.274) 204.149,200.274 204.149,200.473 ccw(c204.05,200.473) 204.05,200.572 203.831,200.572 cw(c203.831,200.671) 203.732,200.671 203.732,200.87 cw(c203.831,200.87) 203.831,200.969 204.05,200.969 ccw(c204.05,201.068) 204.149,201.068 204.149,201.267 ccw(c204.05,201.267) 204.05,201.366 203.831,201.366 cw(c203.831,201.465) 203.732,201.465 203.732,201.664 cw(c203.831,201.664) 203.831,201.763 204.15,201.763 ccw(c204.15,201.862) 204.25,201.862 204.25,202.061 ccw(c204.15,202.061) 204.15,202.16 203.831,202.16 cw(c203.831,202.259) 203.732,202.259 203.732,202.458 cw(c203.831,202.458) 203.831,202.557 203.928,202.557 ccw(c203.928,202.656) 204.027,202.656 204.027,202.855 ccw(c203.928,202.855) 203.928,202.954 203.831,202.954 cw(c203.831,203.053) 203.732,203.053 203.732,203.252 cw(c203.831,203.252) 203.831,203.351 204.12,203.351 ccw(c204.12,203.45) 204.22,203.45 204.22,203.649 ccw(c204.12,203.649) 204.12,203.748 203.831,203.748 cw(c203.831,203.847) 203.732,203.847 203.732,204.046 cw(c203.831,204.046) 203.831,204.145 203.933,204.145 ccw(c203.933,204.244) 204.032,204.244 204.032,204.443 ccw(c203.933,204.443) 203.933,204.542 203.831,204.542 cw(c203.831,204.641) 203.732,204.641 203.732,204.84 cw(c203.831,204.84) 203.831,204.939 204.101,204.939 ccw(c204.101,205.038) 204.2,205.038 204.2,205.237 ccw(c204.101,205.237) 204.101,205.336 203.831,205.336 cw(c203.831,205.435) 203.732,205.435 203.732,207.442 203.732,210.011 203.88,210.158 203.88,210.598 204.114,210.833 204.737,210.833 204.948,211.044 v15(205.191,211.044)
DDR4_ALERT_N: R58.1 U1.AB24 U8.P6 U9.P6 U10.P6 U11.P6
DDR4_BA0: R32.1 U1.AD27 U8.N2 U9.N2 U10.N2 U11.N2 | length 92.8
  L1 w0.116: U9.N2@171.206,213.048 v2(171.609,213.452) ; U11.N2@182.666,213.048 v2(183.07,213.452) ; v6(184.442,189.306) 184.442,189.442 U1.AD27@184.927,189.927 ; U10.N2@194.127,213.048 v2(194.53,213.452) ; U8.N2@205.587,213.048 v15(205.969,213.429)
  L5 (Sign) w0.092: 170.156,213.081 170.526,213.081 170.897,213.452 v2(171.609,213.452) 172.397,213.452 172.781,213.068 182.268,213.068 182.652,213.452 v2(183.07,213.452) 183.601,213.452 183.967,213.086 193.617,213.086 193.982,213.452 v2(194.53,213.452) ; 195.809,213.452 v2(194.53,213.452) ; v15(205.969,213.429) 205.55,213.429 205.177,213.056 202.184,213.056 201.848,213.056 cw(c201.848,213.115) 201.789,213.115 ccw(c201.699,213.115) 201.699,213.204 201.43,213.204 ccw(c201.43,213.115) 201.341,213.115 cw(c201.282,213.115) 201.282,213.056 201.117,213.056 200.721,213.452 200.587,213.452 ccw(c200.587,213.362) 200.497,213.362 200.497,212.925 cw(c200.407,212.925) 200.407,212.836 200.139,212.836 cw(c200.139,212.925) 200.049,212.925 200.049,213.452 200.049,213.598 ccw(c199.96,213.598) 199.96,213.687 199.691,213.687 ccw(c199.691,213.598) 199.601,213.598 199.601,213.452 199.601,212.925 cw(c199.512,212.925) 199.512,212.836 199.243,212.836 cw(c199.243,212.925) 199.154,212.925 199.154,213.452 199.154,213.598 ccw(c199.064,213.598) 199.064,213.687 198.795,213.687 ccw(c198.795,213.598) 198.706,213.598 198.706,213.452 198.706,213.148 cw(c198.616,213.148) 198.616,213.058 198.348,213.058 cw(c198.348,213.148) 198.258,213.148 198.258,213.452 198.258,213.598 ccw(c198.168,213.598) 198.168,213.687 197.9,213.687 ccw(c197.9,213.598) 197.81,213.598 197.81,213.452 197.81,213.229 cw(c197.721,213.229) 197.721,213.14 197.452,213.14 cw(c197.452,213.229) 197.362,213.229 197.362,213.362 ccw(c197.273,213.362) 197.273,213.452 196.215,213.452 v2(194.53,213.452)
  L3 (Sign) w0.092: v6(184.442,189.306) 184.442,189.043 184.842,188.643 184.842,188.216 185.279,187.779 185.286,187.785 185.618,187.785 188.209,185.195 192.021,185.195 192.06,185.233 192.068,185.233 206.772,199.937 206.772,200.037 ccw(c206.672,200.037) 206.672,200.136 206.412,200.136 cw(c206.412,200.235) 206.313,200.235 206.313,200.434 cw(c206.412,200.434) 206.412,200.533 206.772,200.533 207.132,200.533 ccw(c207.132,200.632) 207.231,200.632 207.231,200.831 ccw(c207.132,200.831) 207.132,200.93 206.871,200.93 cw(c206.871,201.029) 206.772,201.029 206.772,201.228 cw(c206.871,201.228) 206.871,201.327 207.132,201.327 ccw(c207.132,201.426) 207.231,201.426 207.231,201.625 ccw(c207.132,201.625) 207.132,201.724 206.871,201.724 cw(c206.871,201.823) 206.772,201.823 206.772,202.286 206.772,212.392 206.195,212.968 206.195,213.203 v15(205.969,213.429)
DDR4_BA1: R34.1 U1.AC26 U8.N5 U9.N5 U10.N5 U11.N5 | length 88.6
  L1 w0.116: U9.N5@166.406,213.048 166.802,213.445 v1(166.805,213.445) ; U11.N5@177.866,213.048 178.263,213.445 v2(178.265,213.445) ; v6(183.44,189.414) U1.AC26@183.927,188.927 ; U10.N5@189.327,213.048 189.723,213.445 v2(189.726,213.445) ; U8.N5@200.787,213.048 201.184,213.445 v2(201.186,213.445)
  L12 (Sign) w0.092: 165.872,213.848 166.275,213.445 v1(166.805,213.445) 167.041,213.445 167.389,213.792 171.999,213.792 172.346,213.445 v2(178.265,213.445) 178.511,213.69 178.857,213.69 178.932,213.765 178.943,213.765 179.046,213.868 184.053,213.868 184.511,214.325 188.316,214.325 189.196,213.445 189.988,213.445 190.335,213.792 191.16,213.792 194.92,213.792 195.517,213.195 195.618,213.195 195.631,213.195 196.253,213.195 198.593,213.195 ccw(c198.593,213.284) 198.683,213.284 198.683,213.396 cw(c198.773,213.396) 198.773,213.486 199.041,213.486 cw(c199.041,213.396) 199.131,213.396 199.131,213.195 199.131,213.032 ccw(c199.22,213.032) 199.22,212.942 199.489,212.942 ccw(c199.489,213.032) 199.579,213.032 199.579,213.195 199.579,213.396 cw(c199.668,213.396) 199.668,213.486 199.937,213.486 cw(c199.937,213.396) 200.026,213.396 200.026,213.195 200.026,213.032 ccw(c200.116,213.032) 200.116,212.942 200.385,212.942 ccw(c200.385,213.032) 200.474,213.032 200.474,213.105 cw(c200.564,213.105) 200.564,213.195 200.698,213.195 200.948,213.445 v2(201.186,213.445)
  L3 (Sign) w0.092: v6(183.44,189.414) 183.44,190.068 183.892,190.52 183.892,191.461 183.632,191.721 183.632,191.768 183.173,192.227 183.093,192.307 183.093,192.573 183.281,192.761 183.464,192.761 183.694,192.991 183.937,192.991 184.039,193.093 185.28,193.093 ; 185.281,193.093 185.644,193.093 186.065,193.514 188.066,195.547 188.278,195.762 cw(c188.349,195.692) 188.419,195.763 188.512,195.671 ccw(c188.582,195.742) 188.653,195.672 188.792,195.814 ccw(c188.721,195.883) 188.791,195.954 188.626,196.116 188.1,196.634 cw(c188.17,196.704) 188.099,196.774 188.239,196.915 cw(c188.309,196.846) 188.379,196.916 188.905,196.399 ccw(c188.975,196.469) 189.045,196.4 189.185,196.541 ccw(c189.114,196.611) 189.183,196.682 188.662,197.195 cw(c188.731,197.266) 188.661,197.335 188.8,197.477 cw(c188.871,197.407) 188.94,197.478 189.391,197.034 ccw(c189.461,197.105) 189.532,197.035 189.671,197.177 ccw(c189.6,197.246) 189.67,197.317 189.223,197.756 cw(c189.293,197.827) 189.222,197.897 189.361,198.038 cw(c189.432,197.969) 189.502,198.039 189.948,197.6 ccw(c190.018,197.671) 190.089,197.601 190.298,197.813 190.437,197.955 192.204,199.721 192.204,209.132 192.552,209.481 192.552,209.598 192.769,209.815 192.794,209.815 192.794,209.84 192.821,209.867 193.346,209.867 193.616,210.137 193.649,210.137 194.16,210.648 195.24,210.648 200.757,216.166 201.876,216.166 202.387,215.654 202.387,214.02 202.197,213.83 201.913,213.83 201.528,213.445 v2(201.186,213.445)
